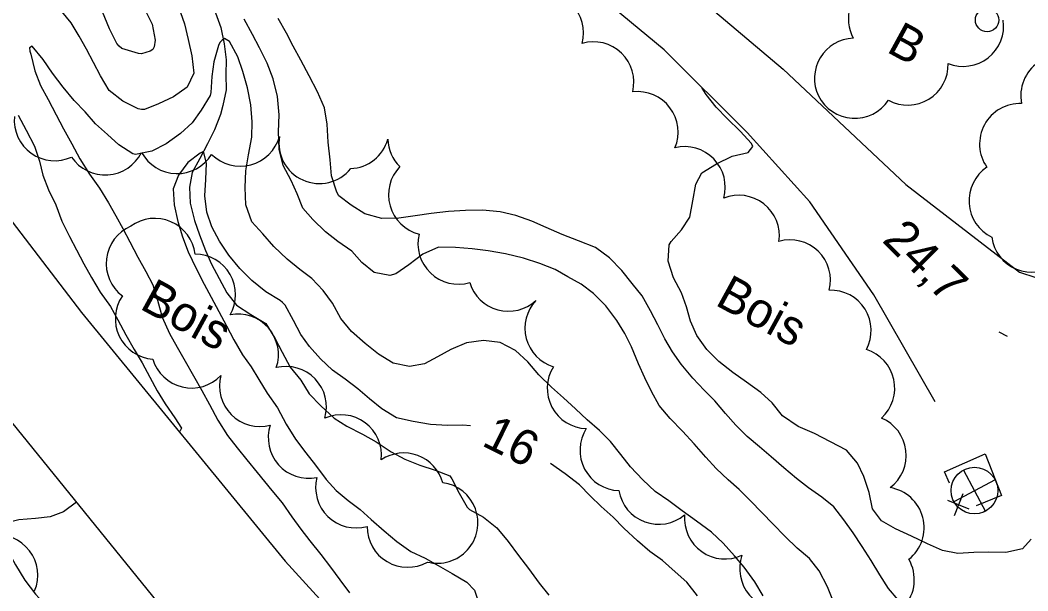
# Model space of a CAD drawing. Extents: x 219136 to 222520, y 5421589 to 5424530.
# Drawn here: x 220232.7 to 220319, y 5423622.9 to 5423671.8 of the extents above; entities that cross this region are included whole.
import ezdxf

# ---------------------------------------------------------------- set-up
doc = ezdxf.new("R2010")
doc.units = 0
for name, color, linetype in [('Level 1', 7, 'Continuous'), ('Level 19', 7, 'Continuous'), ('Level 2', 7, 'Continuous'), ('Level 21', 7, 'Continuous'), ('Level 3', 7, 'Continuous'), ('Level 34', 7, 'Continuous'), ('Level 36', 7, 'Continuous'), ('Level 37', 7, 'Continuous'), ('Level 4', 7, 'Continuous'), ('Level 44', 7, 'Continuous')]:
    doc.layers.add(name, color=color, linetype=linetype)

msp = doc.modelspace()

# ---------------------------------------------------------------- linework, layer by layer
at = {"layer": 'Level 1'}
for points in [[(220246.28, 5423672.9), (220246.79, 5423671.44), (220247.1, 5423670.11), (220247.41, 5423668.71), (220247.6, 5423667.22), (220247.01, 5423666.02), (220245.85, 5423665.2), (220244.57, 5423664.59), (220243.38, 5423664.1), (220243.12, 5423664.1), (220242.83, 5423664.17), (220241.52, 5423664.81), (220240.34, 5423665.72), (220239.61, 5423667), (220239.01, 5423668.12), (220238.4, 5423669.26), (220237.79, 5423670.39), (220237.09, 5423671.54), (220236.28, 5423672.5)], [(220256.93, 5423655.67), (220256.43, 5423656.88), (220255.91, 5423658.02), (220255.25, 5423659.31), (220254.89, 5423660.71), (220254.84, 5423662.19), (220254.89, 5423663.64), (220254.74, 5423665.21), (220254.38, 5423666.74), (220253.88, 5423668.06), (220253.22, 5423669.38), (220252.6, 5423670.54), (220251.9, 5423671.85)], [(220232.55, 5423663.62), (220233.24, 5423662.34), (220233.95, 5423660.98), (220234.38, 5423659.7), (220234.66, 5423658.48), (220235.15, 5423657.24), (220235.79, 5423655.96), (220236.3, 5423654.54), (220236.94, 5423653.24), (220237.54, 5423652.11), (220238.19, 5423650.89), (220238.84, 5423649.74), (220239.58, 5423648.46), (220240.46, 5423647.24), (220241.09, 5423646.11), (220241.78, 5423644.82), (220242.48, 5423643.57), (220243.17, 5423642.43), (220243.82, 5423641.21), (220244.46, 5423640.02), (220245.14, 5423638.92), (220245.96, 5423637.73), (220246.54, 5423636.83), (220246.42, 5423636.6), (220246.35, 5423636.51)], [(220302.39, 5423621.84), (220301.83, 5423623.25), (220301.12, 5423624.63), (220300.27, 5423625.68), (220299.23, 5423626.57), (220298.19, 5423627.55), (220297.16, 5423628.64), (220296.22, 5423629.59), (220295.22, 5423630.64), (220294.27, 5423631.58), (220293.31, 5423632.42), (220292.3, 5423633.38), (220291.41, 5423634.34), (220290.42, 5423635.49), (220289.42, 5423636.58), (220288.35, 5423637.66), (220287.43, 5423638.78), (220286.77, 5423639.98), (220286.19, 5423641.14), (220285.65, 5423642.34), (220285.05, 5423643.79), (220284.47, 5423644.93), (220283.8, 5423646.05), (220282.86, 5423647.29), (220281.8, 5423648.37), (220280.75, 5423649.15), (220279.61, 5423649.78), (220278.53, 5423650.41), (220277.21, 5423650.93), (220275.8, 5423651.37), (220274.27, 5423651.75), (220272.79, 5423652.02), (220271.41, 5423652.17), (220269.99, 5423652.31), (220268.54, 5423652.33), (220267.18, 5423651.72), (220265.99, 5423650.82), (220264.89, 5423650.03), (220264.37, 5423649.89), (220263.02, 5423650.16), (220261.97, 5423651.02), (220261.1, 5423651.97), (220259.92, 5423652.82), (220258.86, 5423653.64), (220257.78, 5423654.68), (220256.93, 5423655.67)], [(220237.54, 5423630.51), (220236.43, 5423629.68), (220235.29, 5423629.24), (220234.03, 5423629.09), (220232.62, 5423629), (220231.81, 5423628.8), (220230.95, 5423627.95), (220231.54, 5423626.59), (220232.32, 5423625.14), (220233.13, 5423623.83), (220234.04, 5423622.64), (220234.97, 5423621.61), (220235.87, 5423620.53), (220236.76, 5423619.34), (220237.56, 5423618.24), (220238.46, 5423617.12)]]:
    msp.add_lwpolyline(points, dxfattribs=at)
at = {"layer": 'Level 19'}
for points in [[(220264.95, 5423720.37), (220259.8, 5423716.84), (220255.97, 5423712.71), (220254.12, 5423708.94), (220255.03, 5423704.95), (220257.6, 5423701.67), (220265.26, 5423695.03), (220275.33, 5423686.76), (220285.43, 5423678.24), (220298.03, 5423667.55), (220308.54, 5423657.7), (220318.25, 5423650.18), (220322.45, 5423648.81), (220325.52, 5423649.35)], [(220311.04, 5423639.1), (220305.79, 5423648.24), (220300.3, 5423656.2), (220294.95, 5423662.15), (220287.84, 5423669.22), (220279.13, 5423676.45), (220270.01, 5423684.09), (220260.19, 5423692.4), (220252.45, 5423699.58), (220247.71, 5423703.48), (220243.53, 5423705.31), (220240.33, 5423705.38), (220235.75, 5423704.46), (220229.88, 5423702.71), (220221.09, 5423699.88), (220215.03, 5423697.75), (220211.43, 5423695.68), (220206.39, 5423692.74)]]:
    msp.add_lwpolyline(points, dxfattribs=at)
at = {"layer": 'Level 2'}
for points in [[(220243.38, 5423672.71), (220244.02, 5423671.4), (220244.28, 5423670.03), (220244.2, 5423669.47), (220244.07, 5423669.24), (220243.86, 5423669.11), (220243.11, 5423668.86), (220242.85, 5423668.9), (220241.44, 5423669.34), (220241.2, 5423669.52), (220241.01, 5423669.75), (220240.37, 5423671.02), (220239.78, 5423672.47)], [(220306.31, 5423624.29), (220305.55, 5423625.51), (220304.8, 5423626.7), (220304.01, 5423627.88), (220303.22, 5423628.98), (220302.36, 5423630.1), (220301.34, 5423630.94), (220300.2, 5423631.73), (220299.17, 5423632.52), (220298.09, 5423633.45), (220297.01, 5423634.38), (220296.01, 5423635.23), (220294.95, 5423636.12), (220293.99, 5423637.08), (220293.1, 5423638.09), (220292.17, 5423639.16), (220291.27, 5423640.08), (220290.31, 5423641.11), (220289.31, 5423642.3), (220288.55, 5423643.36), (220287.9, 5423644.48), (220287.29, 5423645.67), (220286.69, 5423646.87), (220285.97, 5423648.15), (220285.11, 5423649.21), (220284.23, 5423650.33), (220283.17, 5423651.41), (220281.97, 5423652.29), (220280.52, 5423652.87), (220279.11, 5423653.4), (220277.75, 5423654), (220276.51, 5423654.54), (220275.15, 5423655.04), (220273.82, 5423655.36), (220272.31, 5423655.49), (220270.85, 5423655.45), (220269.39, 5423655.38), (220267.91, 5423655.22), (220266.53, 5423655), (220265.14, 5423654.82), (220263.67, 5423654.77), (220262.22, 5423655.17), (220261.07, 5423655.92), (220260.01, 5423656.73), (220259.83, 5423657.02), (220259.38, 5423658.44), (220259.26, 5423659.8), (220259.1, 5423661.32), (220258.99, 5423662.86), (220258.77, 5423664.26), (220258.18, 5423665.63), (220257.46, 5423666.99), (220256.74, 5423668.32), (220256.1, 5423669.52), (220255.51, 5423670.63), (220254.82, 5423671.91)], [(220236.4, 5423666.03), (220235.5, 5423667.23), (220234.69, 5423668.38), (220233.76, 5423669.54), (220233.54, 5423669.39), (220233.56, 5423669.11), (220233.63, 5423668.84), (220233.97, 5423667.41), (220234.48, 5423666.17), (220235.12, 5423664.96), (220235.82, 5423663.65), (220236.45, 5423662.46), (220237.15, 5423661.16), (220237.83, 5423659.89), (220238.65, 5423658.57), (220239.51, 5423657.37), (220240.29, 5423656.12), (220240.92, 5423655.02), (220241.51, 5423653.92), (220242.12, 5423652.77), (220242.81, 5423651.48), (220243.47, 5423650.25), (220244.07, 5423649.1), (220244.48, 5423647.8), (220244.88, 5423646.34), (220245.52, 5423644.94), (220246.16, 5423643.76), (220246.85, 5423642.56), (220247.55, 5423641.32), (220248.29, 5423640.06), (220248.94, 5423638.85), (220249.65, 5423637.53), (220250.47, 5423636.22), (220251.29, 5423635.16), (220252.14, 5423634.12), (220253.01, 5423633.04), (220254.27, 5423631.5), (220255.14, 5423630.45), (220255.99, 5423629.25), (220256.75, 5423628.18), (220257.52, 5423627.19), (220258.46, 5423626.02), (220259.3, 5423624.93), (220260.09, 5423623.85), (220260.91, 5423622.73)], [(220287.07, 5423631.42), (220286.01, 5423632.4), (220284.96, 5423633.52), (220284.15, 5423634.59), (220283.24, 5423635.69), (220282.31, 5423636.63), (220281.26, 5423637.55), (220280.26, 5423638.48), (220279.24, 5423639.42), (220278.2, 5423640.34), (220277.12, 5423641.41), (220276.18, 5423642.5), (220275.13, 5423643.48), (220273.8, 5423644.18), (220272.39, 5423644.35), (220270.93, 5423644.15), (220269.59, 5423643.56), (220268.44, 5423642.94), (220267.33, 5423642.35), (220266.06, 5423642.12), (220264.66, 5423642.4), (220263.4, 5423643.16), (220262.26, 5423644.09), (220261.09, 5423645.1), (220260.18, 5423646.22), (220259.45, 5423647.53), (220258.65, 5423648.62), (220257.69, 5423649.63), (220256.67, 5423650.42), (220255.59, 5423651.29), (220254.45, 5423652.37), (220253.49, 5423653.47), (220252.55, 5423654.5), (220252.04, 5423655.94), (220251.99, 5423657.42), (220252.03, 5423658.85), (220252.26, 5423660.22), (220252.55, 5423661.73), (220252.59, 5423663.06), (220252.46, 5423664.5), (220252.19, 5423665.97), (220251.79, 5423667.36), (220251.35, 5423668.63), (220250.63, 5423669.92), (220250.23, 5423670.18), (220250.01, 5423670.04), (220249.83, 5423669.84), (220249.69, 5423669.6), (220249.31, 5423668.19), (220249.14, 5423666.92), (220249.06, 5423665.56), (220249, 5423665.3), (220248.22, 5423664.04), (220247.46, 5423662.97), (220246.45, 5423662.04), (220245.21, 5423661.18), (220244, 5423660.55), (220242.6, 5423660.25), (220242.36, 5423660.3), (220241.18, 5423661.07), (220240.19, 5423661.98), (220239.18, 5423662.88), (220238.29, 5423663.9), (220237.36, 5423664.88), (220236.4, 5423666.03)], [(220293.67, 5423660.1), (220295.03, 5423660.43), (220295.42, 5423660.95), (220295.31, 5423661.2), (220294.36, 5423662.26), (220293.23, 5423663.34), (220292.29, 5423664.31), (220291.45, 5423665.39), (220291.1, 5423665.94), (220291.09, 5423665.98)], [(220266.36, 5423637.39), (220264.93, 5423637.73), (220263.69, 5423638.49), (220262.62, 5423639.34), (220261.62, 5423640.19), (220260.54, 5423641.04), (220259.46, 5423641.8), (220258.43, 5423642.78), (220257.48, 5423643.81), (220256.76, 5423644.86), (220256.13, 5423646.05), (220255.4, 5423647.37), (220255.18, 5423647.6), (220254.98, 5423647.75), (220253.74, 5423648.49), (220252.55, 5423649.46), (220251.54, 5423650.5), (220250.6, 5423651.65), (220249.79, 5423652.83), (220249.13, 5423654.07), (220248.71, 5423655.32), (220248.54, 5423656.73), (220248.62, 5423658.12), (220248.67, 5423659.52), (220248.41, 5423660.5), (220248.14, 5423660.38), (220247.07, 5423659.56), (220246.28, 5423658.5), (220245.81, 5423657.32), (220245.9, 5423655.96), (220246.22, 5423654.51), (220246.63, 5423653.21), (220247.12, 5423651.92), (220247.78, 5423650.5), (220248.47, 5423649.16), (220249.07, 5423648.05), (220249.72, 5423646.83), (220250.38, 5423645.58), (220251.02, 5423644.4), (220251.77, 5423643.1), (220252.49, 5423642.07), (220253.16, 5423640.99), (220253.86, 5423639.83), (220254.74, 5423638.58), (220255.5, 5423637.19), (220256.28, 5423635.9), (220257.17, 5423634.73), (220258, 5423633.66), (220258.92, 5423632.44), (220259.77, 5423631.5), (220260.79, 5423630.64), (220261.83, 5423629.87), (220262.78, 5423629.02), (220263.89, 5423628.04), (220264.96, 5423627.14), (220266.15, 5423626.28), (220267.38, 5423625.7), (220268.5, 5423625.09), (220269.69, 5423624.39), (220270.97, 5423623.66), (220271.6, 5423622.97), (220272.08, 5423621.61)], [(220319.25, 5423627.34), (220318.52, 5423626.51), (220317.09, 5423626.18), (220315.63, 5423626.21), (220314.35, 5423626.2), (220312.97, 5423626.11), (220311.68, 5423626.36), (220310.39, 5423626.92), (220309, 5423627.59), (220307.65, 5423628.22), (220306.45, 5423628.91), (220305.67, 5423629.94), (220305.39, 5423631.34), (220304.92, 5423632.71), (220304.39, 5423633.85), (220303.44, 5423634.94), (220302.07, 5423635.65), (220300.7, 5423636.39), (220299.31, 5423636.97), (220297.97, 5423637.89), (220297.1, 5423639), (220296.13, 5423639.9), (220294.9, 5423640.76), (220293.71, 5423641.59), (220292.53, 5423642.53), (220291.51, 5423643.57), (220290.63, 5423644.76), (220290.11, 5423646), (220289.75, 5423647.23), (220289.32, 5423648.42), (220288.65, 5423649.69), (220288.19, 5423651.12), (220288.26, 5423652.53), (220288.44, 5423652.8), (220289.32, 5423653.8), (220290.04, 5423654.88), (220290.29, 5423656.29), (220290.56, 5423657.73), (220291.06, 5423658.69), (220292.32, 5423659.47), (220293.67, 5423660.1)], [(220271.26, 5423637.02), (220270.61, 5423637.09), (220269.31, 5423637.06), (220267.84, 5423637.14), (220266.36, 5423637.39)], [(220290.7, 5423622.48), (220289.78, 5423623.64), (220288.8, 5423624.55), (220287.7, 5423625.5), (220286.63, 5423626.29), (220285.57, 5423627.19), (220284.39, 5423628.27), (220283.47, 5423629.21), (220282.45, 5423630.12), (220281.51, 5423631.05), (220280.59, 5423631.98), (220279.37, 5423632.92), (220278.13, 5423633.8)], [(220296.31, 5423622.47), (220295.61, 5423623.67), (220294.7, 5423624.93), (220293.87, 5423625.92), (220292.89, 5423626.99), (220291.89, 5423627.93), (220290.6, 5423628.86), (220289.39, 5423629.76), (220288.24, 5423630.62), (220287.07, 5423631.42)], [(220319.39, 5423619.31), (220318.13, 5423618.63), (220316.58, 5423618.35), (220315.3, 5423618.16), (220313.89, 5423617.79), (220312.49, 5423617.59), (220311.05, 5423617.56), (220310.79, 5423617.73), (220310.66, 5423617.95), (220310.47, 5423618.51), (220309.98, 5423619.92), (220308.92, 5423621.1), (220307.86, 5423622.14), (220307.05, 5423623.11), (220306.31, 5423624.29)]]:
    msp.add_lwpolyline(points, dxfattribs=at)
at = {"layer": 'Level 21'}
for points in [[(220166.94, 5423796.4), (220165.45, 5423791.9), (220164.79, 5423788.61), (220164.68, 5423785.13), (220166.36, 5423777.99), (220171.96, 5423763.6), (220181.28, 5423741.23), (220188.27, 5423726.12), (220196.66, 5423710.1), (220205.15, 5423694.82), (220212.75, 5423682.11), (220221.66, 5423668.47), (220230.52, 5423656.43), (220237.97, 5423646.72), (220255.42, 5423625.45), (220266.37, 5423613.44), (220281.41, 5423597.94)], [(220368.33, 5423520.62), (220355.57, 5423527.31), (220349.18, 5423530.75), (220341.18, 5423535.53), (220335.39, 5423539.32), (220330.34, 5423542.3), (220326.15, 5423545.14), (220314.08, 5423553.8), (220301.96, 5423563.7), (220292.71, 5423571.85), (220283, 5423581.35), (220270.61, 5423593.91), (220257.53, 5423607.42), (220244.93, 5423621.4), (220229.8, 5423640.05), (220216.29, 5423658.26), (220203.07, 5423678.22)]]:
    msp.add_lwpolyline(points, dxfattribs=at)
at = {"layer": 'Level 3'}
msp.add_line((220316.5, 5423645.08), (220317.2, 5423644.7), dxfattribs=at)
at = {"layer": 'Level 34'}
for p, q in [((220313.46, 5423633.25), (220315.34, 5423629.71)), ((220316.17, 5423632.42), (220312.63, 5423630.54))]:
    msp.add_line(p, q, dxfattribs=at)
msp.add_circle((220314.403, 5423631.491), 2, dxfattribs=at)
at = {"layer": 'Level 36'}
msp.add_circle((220315.484, 5423671.767), 1, dxfattribs=at)
at = {"layer": 'Level 37'}
for p, q in [((220313.96, 5423629.89), (220312.11, 5423630.65)), ((220313.42, 5423631.2), (220312.66, 5423629.34))]:
    msp.add_line(p, q, dxfattribs=at)
for points in [[(220311.85, 5423633.11), (220315.33, 5423634.65), (220316.73, 5423631.06), (220314.55, 5423630.2)], [(220312.27, 5423632.12), (220311.85, 5423633.11)]]:
    msp.add_lwpolyline(points, dxfattribs=at)
at = {"layer": 'Level 4'}
for points in [[(220249.45, 5423672.39), (220249.9, 5423671.12), (220250.19, 5423669.74), (220250.37, 5423668.35), (220250.32, 5423667.1), (220250.35, 5423665.8), (220250.06, 5423664.45), (220249.88, 5423663.67), (220249.37, 5423662.37), (220248.76, 5423661.16), (220248.11, 5423659.91), (220247.44, 5423658.72), (220247.22, 5423657.45), (220247.27, 5423656.09), (220247.66, 5423654.62), (220248.09, 5423653.37), (220248.6, 5423652.04), (220249.1, 5423650.86), (220249.75, 5423649.64), (220250.41, 5423648.42), (220251.24, 5423647.35), (220252.47, 5423646.57), (220253.74, 5423645.79), (220254.52, 5423644.53), (220255.16, 5423643.33), (220255.85, 5423642.05), (220256.76, 5423640.94), (220257.46, 5423639.77), (220258.45, 5423638.74), (220259.6, 5423637.7), (220260.69, 5423637), (220262.04, 5423636.31), (220263.21, 5423635.65), (220264.47, 5423634.81), (220265.66, 5423634.17), (220266.92, 5423633.67), (220268.24, 5423633.23), (220269.51, 5423632.74), (220269.66, 5423632.49), (220270.29, 5423631.26)], [(220270.29, 5423631.26), (220270.99, 5423630.06), (220271.19, 5423629.86), (220272.37, 5423629.21), (220273.51, 5423628.31), (220274.48, 5423627.14), (220275.39, 5423625.93), (220276.24, 5423624.81), (220277.14, 5423623.58), (220277.98, 5423622.53)]]:
    msp.add_lwpolyline(points, dxfattribs=at)
at = {"layer": 'Level 44'}
for centre, start, end in [((220307.074, 5423671.852), 116.32308, 208.16351), ((220277.473, 5423670.655), 345.1181, 105.1181), ((220313.436, 5423671.26), 248.22184, 8.22184), ((220281.788, 5423666.439), 346.20907, 106.20907), ((220304.18, 5423666.756), 92.63106, 205.47314), ((220321.832, 5423665.284), 58.07746, 191.13598), ((220308.688, 5423667.946), 241.60168, 1.60168), ((220285.576, 5423662.175), 337.04202, 97.04203), ((220304.153, 5423666.811), 206.48669, 326.48669), ((220318.304, 5423661.153), 87.86222, 215.04466), ((220235.683, 5423663.188), 174.70049, 294.70049), ((220251.574, 5423662.711), 224.79705, 344.79705), ((220258.334, 5423661.234), 170.55297, 320.93191), ((220260.87, 5423662.511), 272.53131, 344.03595), ((220267.663, 5423661.684), 182.07955, 225.37716), ((220289.611, 5423657.464), 344.11693, 104.11693), ((220240.011, 5423661.966), 213.75147, 333.75147), ((220246.164, 5423662.083), 208.43413, 328.43413), ((220267.716, 5423656.807), 135.87378, 255.87378), ((220317.402, 5423656.29), 123.93079, 243.93079), ((220294.239, 5423653.304), 351.97721, 111.97721), ((220244.257, 5423651.328), 6.58459, 126.58459), ((220243.552, 5423650.923), 113.10258, 233.10258), ((220270.235, 5423652.621), 166.19669, 286.19669), ((220319.313, 5423653.639), 187.63926, 307.63926), ((220298.618, 5423649.489), 345.89311, 105.89311), ((220247.696, 5423648.261), 329.9499, 89.9499), ((220274.513, 5423650.31), 197.05404, 312.64108), ((220244.333, 5423646.199), 145.66956, 265.66956), ((220302.099, 5423645.182), 332.00232, 92.00232), ((220279.395, 5423645.402), 137.05404, 252.64108), ((220251.369, 5423643.129), 341.22737, 101.22737), ((220304.113, 5423640.253), 312.45733, 72.45733), ((220247.392, 5423643.733), 196.56294, 316.56294), ((220255.477, 5423638.65), 343.84653, 103.84653), ((220281.299, 5423640.259), 147.99386, 267.99386), ((220253.251, 5423640.445), 164.84797, 284.84797), ((220260.194, 5423634.513), 353.64329, 113.64329), ((220305.099, 5423634.508), 307.00844, 67.00844), ((220257.426, 5423636.006), 161.63826, 281.63826), ((220284.106, 5423634.947), 147.71205, 267.71205), ((220265.559, 5423631.248), 15.40677, 123.71299), ((220261.482, 5423631.758), 165.70994, 285.70994), ((220268.437, 5423628.735), 255.8248, 82.33796), ((220287.382, 5423632.073), 189.75789, 309.75789), ((220306.634, 5423628.322), 308.41328, 80.85914), ((220293.048, 5423629.101), 174.87953, 294.87953), ((220265.884, 5423628.392), 179.48724, 299.48724), ((220230.765, 5423624.239), 337.44757, 97.44757), ((220297.773, 5423624.809), 160.62545, 280.62545), ((220305.793, 5423623.863), 245.75129, 30.24577)]:
    msp.add_arc(centre, 3.464, start, end, dxfattribs=at)

# ---------------------------------------------------------------- texts
at = {"layer": 'Level 2'}
msp.add_text('16', height=3, rotation=333.74623, dxfattribs=at).set_placement((220272.13, 5423635.39))
at = {"layer": 'Level 3'}
msp.add_text('24,7', height=2.9999, rotation=315.0872, dxfattribs=at).set_placement((220306.42, 5423652.86))
at = {"layer": 'Level 44'}
for s, p in [('B', (220306.78, 5423669.09)), ('Bois', (220242.86, 5423647.11)), ('Bois', (220292.11, 5423647.43))]:
    msp.add_text(s, height=3, rotation=331.35475, dxfattribs=at).set_placement(p)

doc.saveas('drawing.dxf')
